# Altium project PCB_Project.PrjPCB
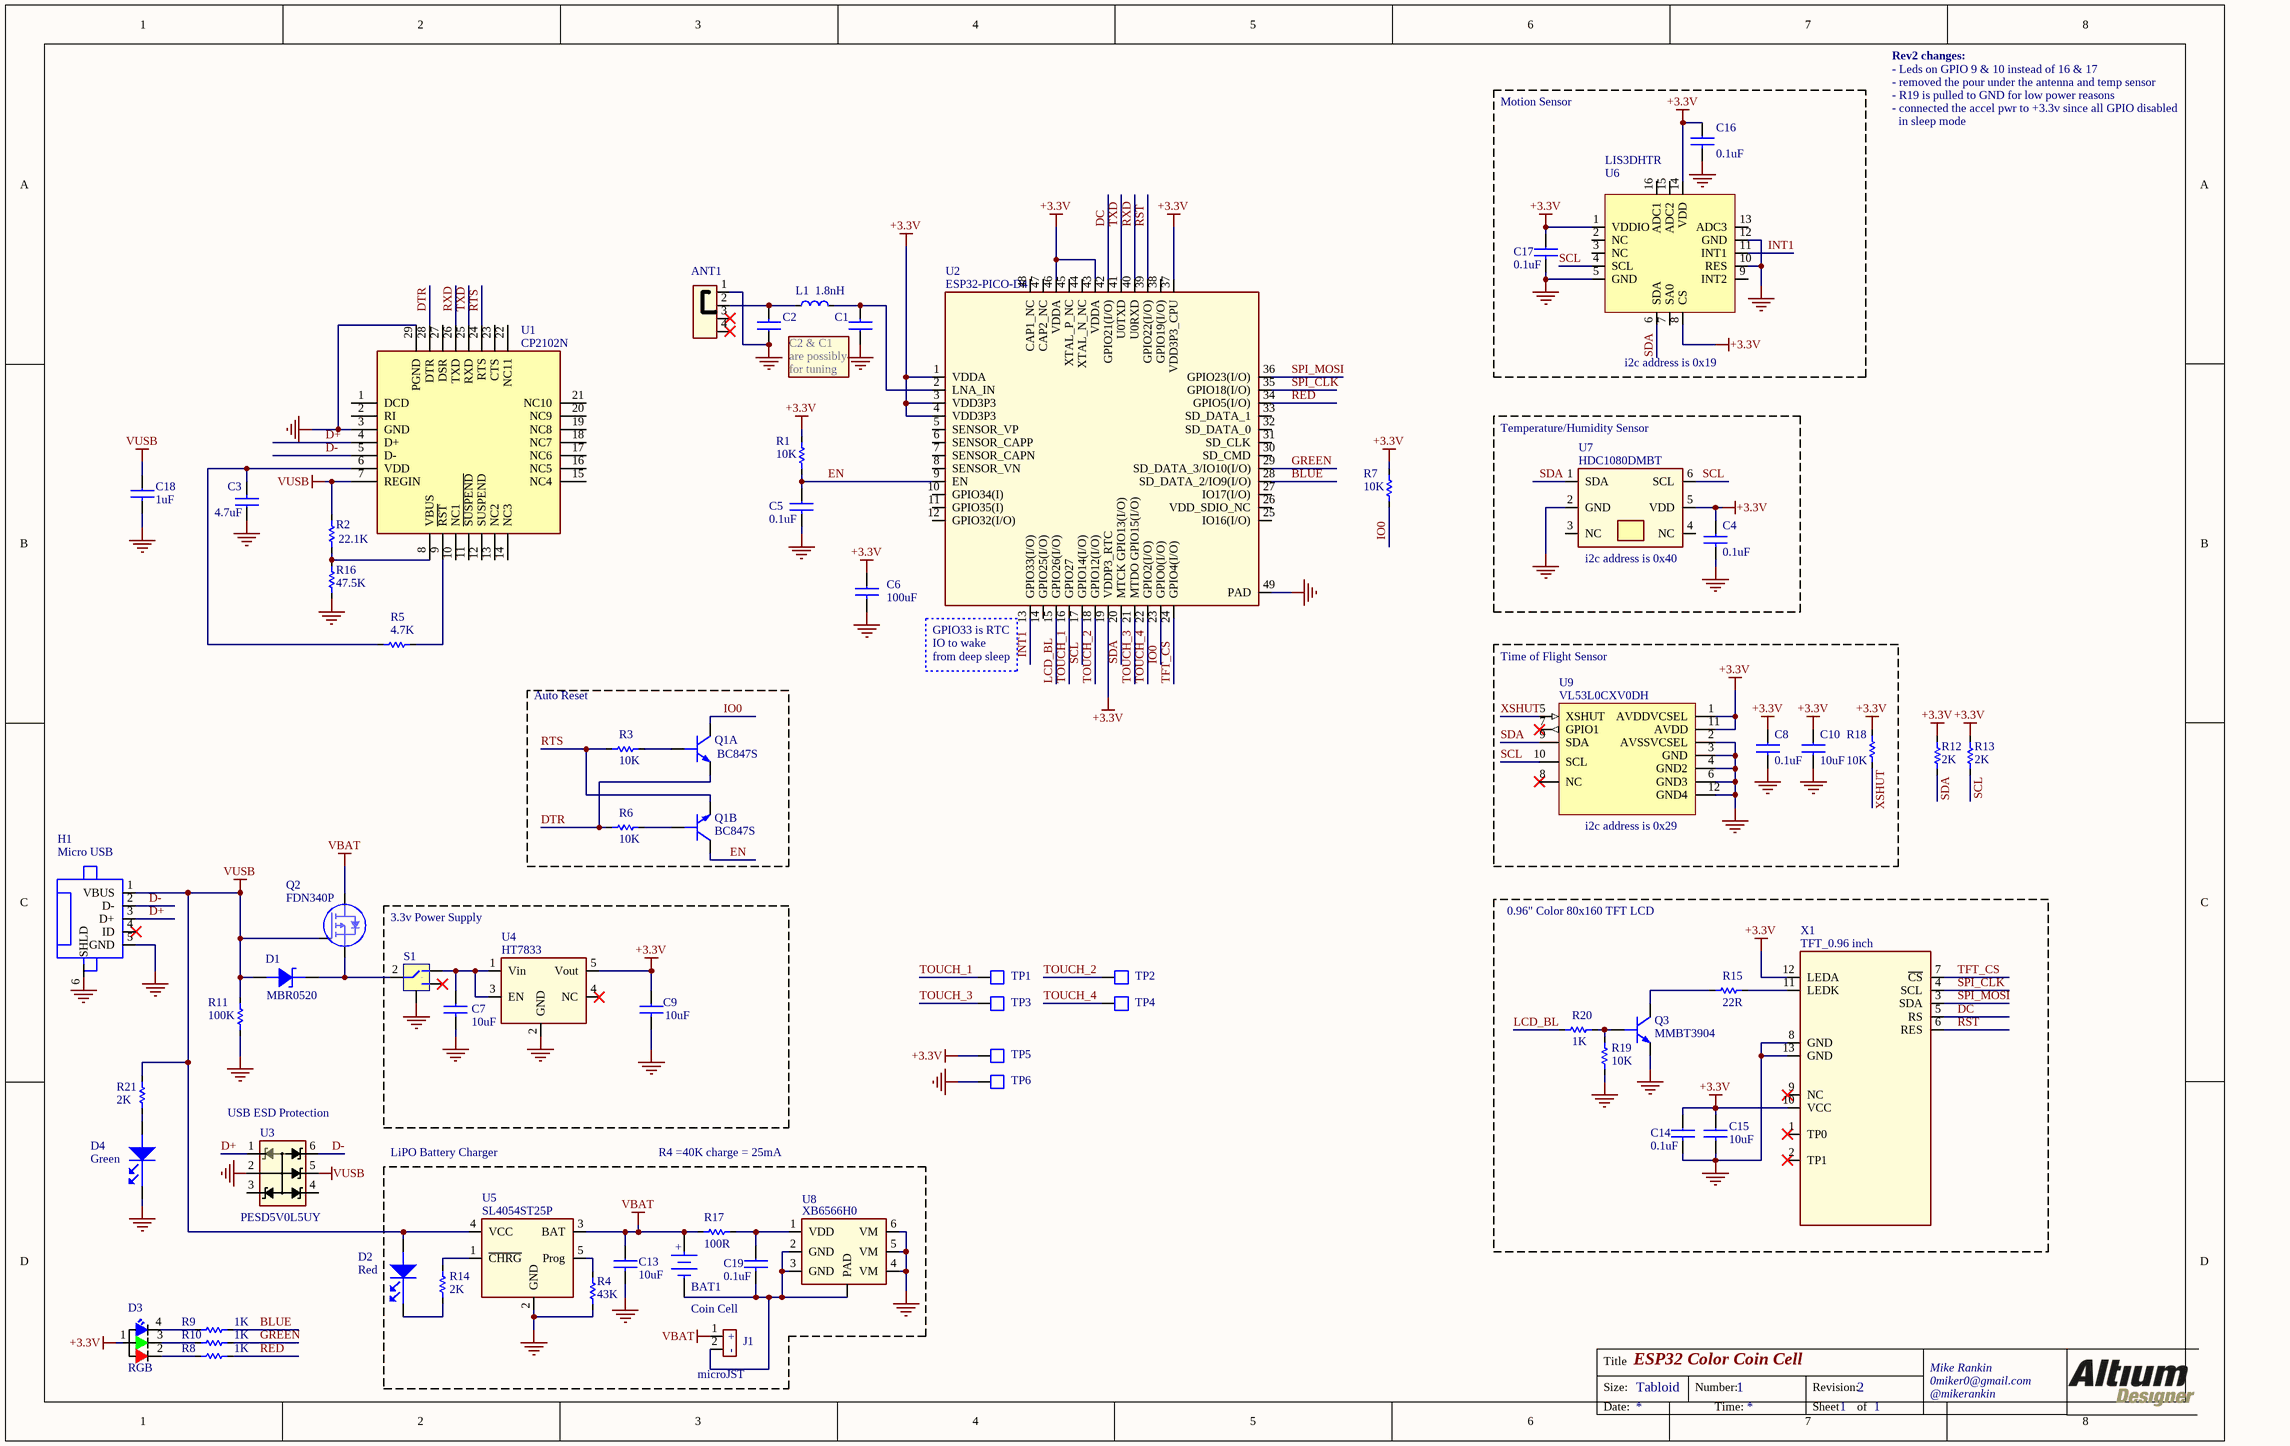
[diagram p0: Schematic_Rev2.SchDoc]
1 sheet, 67 parts. Net scope: global (net labels, ports and power ports of the same name join across sheets).
Board file: PCB_Rev2.PcbDoc

## Sheet Schematic_Rev2.SchDoc: ESP32 Color Coin Cell
size Tabloid; DrawnBy: x; Engineer: x; Address1: Mike Rankin; Address2: 0miker0@gmail.com; Address3: @mikerankin; DocumentNumber: 1; Revision: 2; SheetNumber: 1; SheetTotal: 1

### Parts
ANT1  RF ANT 2.4GHZ STAMPED MET SLD  [PRO-OB-440]  (value not drawn)
BAT1  BATTERY-HOLDER (2450)  [BU2450SM-JJ-GTR]  (value not drawn)
C1  (no value)  [CAPC1005X56N]  (no BOM)
C2  (no value)  [CAPC1005X56N]  (no BOM)
C3  4.7uF  [CAPC1005X56N]
C4  0.1uF  [CAPC1005X56N]
C5  0.1uF  [CAPC1005X56N]
C6  100uF  [CAPC3216X160L]
C7  10uF  [CAPC2012X140N]
C8  0.1uF  [CAPC1005X56N]
C9  10uF  [CAPC2012X140N]
C10  10uF  [CAPC2012X140N]
C13  10uF  [CAPC2012X140N]
C14  0.1uF  [CAPC1005X56N]
C15  10uF  [CAPC2012X140N]
C16  0.1uF  [RESC1005X40L]
C17  0.1uF  [CAPC1005X56N]
C18  1uF  [CAPC1005X56N]
C19  0.1uF  [CAPC1005X56N]
D1  MBR0520  [SOD123]
D2  value Red  [LED1608X55N-RED]  (hidden comment: LED_0603)
D3  RGB  [FC-B1010RGBT-HG]
D4  value Green  [LED1608X55N-GREEN]  (hidden comment: LED_0603)
H1  Micro USB  [1981584-1]
J1  CON2  [JST_Micro_2PIN]  (value not drawn)  (no BOM)
L1  value 1.8nH  [RESC1005X40L]  (hidden comment: Inductor)
Q1  BC847S  [SOT65P210X110-6N]  (parts A,B of 2)
Q2  FDN340P  [SOT95P240X110-3N]
Q3  MMBT3904  [SOT95P240X110-3N]
R1  10K  [RESC1005X40L]
R2  22.1K  [RESC1005X40L]
R3  10K  [RESC1005X40L]
R4  43K  [RESC1005X40L]
R5  4.7K  [RESC1005X40L]
R6  10K  [RESC1005X40L]
R7  10K  [RESC1005X40L]
R8  1K  [RESC1005X40L]
R9  1K  [RESC1005X40L]
R10  1K  [RESC1005X40L]
R11  100K  [RESC1005X40L]
R12  2K  [RESC1005X40L]
R13  2K  [RESC1005X40L]
R14  2K  [RESC1005X40L]
R15  22R  [RESC1005X40L]
R16  47.5K  [RESC1005X40L]
R17  100R  [RESC1005X40L]
R18  10K  [RESC1005X40L]
R19  10K  [RESC1005X40L]
R20  1K  [RESC1005X40L]
R21  2K  [RESC1005X40L]
S1  SWITCH SLIDE  [K3-1296S-E1]  (value not drawn)
TP1  Test Point, 1mm Top Layer  [TP100TL]  (value not drawn)  (no BOM)
TP2  Test Point, 1mm Top Layer  [TP100TL]  (value not drawn)  (no BOM)
TP3  Test Point, 1mm Top Layer  [TP100TL]  (value not drawn)  (no BOM)
TP4  Test Point, 1mm Top Layer  [TP100TL]  (value not drawn)  (no BOM)
TP5  Test Point, 1mm Top Layer  [TP100TL]  (value not drawn)  (no BOM)
TP6  Test Point, 1mm Top Layer  [TP100TL]  (value not drawn)  (no BOM)
U1  CP2102N  [28-QFN]
U2  ESP32-PICO-D4  [QFN48]
U3  PESD5V0L5UY  [SOT65P210X110-6N]
U4  HT7833  [SOT95P280X144-5N]
U5  SL4054ST25P  [SOT95P280X144-5N]
U6  LIS3DHTR  [QFN3X3_16_1.2]
U7  HDC1080DMBT  [HDC1080]
U8  XB6566H0  [DFN-6 2x2mm]
U9  VL53L0CXV0DH  [VL53L0CXV0DH]
X1  TFT_0.96 inch  [TFT_GLASS 0.96 INCH]

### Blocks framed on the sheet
Auto Reset: Q1 R3 R6
3.3v Power Supply: C7 C9 S1 U4
0.96" Color 80x160 TFT LCD: C14 C15 Q3 R15 R19 R20 X1

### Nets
+3.3V: C4.1 C6.1 C8.1 C9.1 C10.1 C14.1 C15.1 C16.1 C17.1 D3.1 R1.1 R7.1 R12.2 R13.2 R18.1 TP5.1 U2.1(VDDA) U2.3(VDD3P3) U2.4(VDD3P3) U2.19(VDDP3_RTC) U2.37(VDD3P3_CPU) U2.43(VDDA) U2.46(VDDA) U4.5(Vout) U6.1(VDDIO) U6.8(CS) U6.14(VDD) U7.5(VDD) U9.1(AVDDVCSEL) U9.11(AVDD) X1.10(VCC) X1.12(LEDA)
GND: ANT1.1 C1.1 C2.1 C3.1 C4.2 C5.2 C6.2 C7.2 C8.2 C9.2 C10.2 C13.2 C14.2 C15.2 C16.2 C17.2 C18.2 D4.1(CATHODE) H1.5(GND) H1.6(SHLD) Q3.2(E) R4.2 R11.2 R16.1 R19.2 S1.4 TP6.1 U1.3(GND) U1.29(PGND) U2.49(PAD) U3.2 U4.2(GND) U5.2(GND) U6.5(GND) U6.10(RES) U6.12(GND) U7.2(GND) U8.4(VM) U8.5(VM) U8.6(VM) U9.2(AVSSVCSEL) U9.3(GND) U9.4(GND2) U9.6(GND3) U9.12(GND4) X1.8(GND) X1.13(GND)
VBAT: BAT1.1(+) C13.1 J1.1 Q2.3(D) R17.1 U5.3(BAT)
VUSB: C18.1 D1.2(Annode) D2.2(ANODE) H1.1(VBUS) Q2.1(G) R2.2 R11.1 R21.2 U1.7(REGIN) U3.5 U5.4(VCC)
BLUE: R9.2 U2.28(SD_DATA_2/IO9(I/O))
D+: H1.3(D+) U1.4(D+) U3.1
D-: H1.2(D-) U1.5(D-) U3.6
DC: U2.42(GPIO21(I/O)) X1.5(RS)
DTR: Q1.1(E1) R6.2 U1.28(DTR)
EN: C5.1 Q1.3(C2) R1.2 U2.9(EN)
GREEN: R10.2 U2.29(SD_DATA_3/IO10(I/O))
INT1: U2.13(GPIO33(I/O)) U6.11(INT1)
IO0: Q1.6(C1) R7.2 U2.23(GPIO0(I/O))
LCD_BL: R20.1 U2.15(GPIO26(I/O))
RED: R8.2 U2.34(GPIO5(I/O))
RST: U2.39(GPIO22(I/O)) X1.6(RES)
RTS: Q1.4(E2) R3.2 U1.24(RTS)
RXD: U1.26(TXD) U2.40(U0RXD)
SCL: R13.1 U2.17(GPIO14(I/O)) U6.4(SCL) U7.6(SCL) U9.10(SCL)
SDA: R12.1 U2.20(MTCK_GPIO13(I/O)) U6.6(SDA) U7.1(SDA) U9.9(SDA)
SPI_CLK: U2.35(GPIO18(I/O)) X1.4(SCL)
SPI_MOSI: U2.36(GPIO23(I/O)) X1.3(SDA)
TFT_CS: U2.24(GPIO4(I/O)) X1.7(~{CS})
TOUCH_1: TP1.1 U2.16(GPIO27)
TOUCH_2: TP2.1 U2.18(GPIO12(I/O))
TOUCH_3: TP3.1 U2.21(MTDO_GPIO15(I/O))
TOUCH_4: TP4.1 U2.22(GPIO2(I/O))
TXD: U1.25(RXD) U2.41(U0TXD)
XSHUT: R18.2 U9.5(XSHUT)
NetANT1_2: ANT1.2 C2.2 L1.1
NetBAT1_2: BAT1.2(-) C19.2 J1.2 U8.2(GND) U8.3(GND) U8.7(PAD)
NetC1_2: C1.2 L1.2 U2.2(LNA_IN)
NetC3_2: C3.2 R5.1 U1.6(VDD)
NetC7_1: C7.1 S1.1 U4.1(Vin) U4.3(EN)
NetC19_1: C19.1 R17.2 U8.1(VDD)
NetD1_1: D1.1(Cathode) Q2.2(S) S1.2
NetD2_1: D2.1(CATHODE) R14.1
NetD3_2: D3.2 R8.1
NetD3_3: D3.3 R10.1
NetD3_4: D3.4 R9.1
NetD4_2: D4.2(ANODE) R21.1
NetQ1_2: Q1.2(B1) R3.1
NetQ1_5: Q1.5(B2) R6.1
NetQ3_1: Q3.1(B) R19.1 R20.2
NetQ3_3: Q3.3(C) R15.2
NetR2_1: R2.1 R16.2 U1.8(VBUS)
NetR4_1: R4.1 U5.5(Prog)
NetR5_2: R5.2 U1.9(~{RST})
NetR14_2: R14.2 U5.1(~{CHRG})
NetR15_1: R15.1 X1.11(LEDK)

Not connected (* = marked no-connect by the designer): ANT1 3* 4*; H1 4(ID)*; S1 3*; U1 1(DCD) 2(RI) 10(NC1) 11(~{SUSPEND}) 12(SUSPEND) 13(NC2) 14(NC3) 15(NC4) 16(NC5) 17(NC6) 18(NC7) 19(NC8) 20(NC9) 21(NC10) 22(NC11) 23(CTS) 27(DSR); U2 5(SENSOR_VP) 6(SENSOR_CAPP) 7(SENSOR_CAPN) 8(SENSOR_VN) 10(GPIO34(I)) 11(GPIO35(I)) 12(GPIO32(I/O)) 14(GPIO25(I/O)) 25(IO16(I/O)) 26(VDD_SDIO_NC) 27(IO17(I/O)) 30(SD_CMD) 31(SD_CLK) 32(SD_DATA_0) 33(SD_DATA_1) 38(GPIO19(I/O)) 44(XTAL_N_NC) 45(XTAL_P_NC) 47(CAP2_NC) 48(CAP1_NC); U3 3 4; U4 4(NC)*; U6 2(NC) 3(NC) 7(SA0) 9(INT2) 13(ADC3) 15(ADC2) 16(ADC1); U7 3(NC) 4(NC); U9 7(GPIO1)* 8(NC)*; X1 1(TP0)* 2(TP1)* 9(NC)*

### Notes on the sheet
- Rev2 changes:
- - Leds on GPIO 9 & 10 instead of 16 & 17
- - removed the pour under the antenna and temp sensor
- Motion Sensor
- - R19 is pulled to GND for low power reasons
- - connected the accel pwr to +3.3v since all GPIO disabled
- in sleep mode
- C2 & C1
- are possibly
- for tuning
- (near U6) i2c address is 0x19
- (near U7) Temperature/Humidity Sensor
- i2c address is 0x40
- (near U2) GPIO33 is RTC
- (near U2) IO to wake
- (near U2) from deep sleep
- Time of Flight Sensor
- (near U9) i2c address is 0x29
- (near U3) USB ESD Protection
- LiPO Battery Charger
- R4 =40K charge = 25mA
- Coin Cell
- (near J1) microJST
- Labels drawn without touching a wire or pin: ~{}

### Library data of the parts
ANT1 = PRO-OB-440: Manufacturer: Proant AB; Vendor: Digi-Key
BAT1 = BU2450SM-JJ-GTR: HOLDER,BATT,COIN,24.5MM,SMT; Manufacturer: MPD; Value: Coin Cell Holder; Vendor: LCSC
C1 C2 = CAP_0402: DNP
C3 = CAP_0603: CAP CER 4.7uF 16V 0402; Vendor: LCSC
C4 C5 C8 C17 C19 = CAP_0402: CAP CER 0.1uF 0402; PartNumber: TCC0402X5R104M160AT; Manufacturer: CCTC; Vendor: LCSC
C6 = CAP_1206: CAP CER 100uF 6.3V 1206; PartNumber: JMK316BJ107ML-T; Manufacturer: Taiyo Yuden; Vendor: LCSC
C7 C9 C10 = CAP_0805: CAP 10uF 0805; Manufacturer: Murata; PartNumber: GRM21BB31C106KE15L; Vendor: LCSC
C13 = CAP_0805: CAP CER 10uF 16V 0805; PartNumber: CL21A106KOQNNNG; Manufacturer: Samsung; Vendor: LCSC
C14 C16 = CAP_0402: CAP CER 0.1uF 0402; Vendor: LCSC
C15 = CAP_0805: CAP 10uF 0805; Vendor: LCSC
C18 = CAP_0603: CAP CER 1uF 16V 0402; Vendor: LCSC
D1 = MBR0520-TP: DIODE SCHOTTKY 20V 500MA SOD123; Manufacturer: CJ; Vendor: LCSC
D2 = LED_0603: LED RED CLEAR 0603 SMD; Manufacturer: FNO; PartNumber: FC-DA1608HRK-620D; Vendor: LCSC
D3 = FC-B1010RGBT-HG: LED,RGB LED,SMD,RoHS; Manufacturer: Foshan; Vendor: LCSC; Value: RGB Led
D4 = LED_0603: LED XXXX CLEAR 0603 SMD; Manufacturer: Lite-On; Vendor: Digi-Key
H1 = 1981584-1: CONN RCPT MICRO USB TYPE AB; Manufacturer: REG CON; PartNumber: C21377; Vendor: LCSC
J1 = JST_Micro_CONN_2PIN: JST MIcro CONN 2POS
L1 = Inductor: Inductor 1.8nH 0402; PartNumber: BKW0603UC1N8KGT; Manufacturer: GFBE; Vendor: LCSC
Q1 = BC847S: TRANS 2NPN 44V 0.1A SC-70-6; Manufacturer: Changjiang; Vendor: LCSC
Q2 = FDN340P: MOSFET P-CH 20V 2A SOT-23; Manufacturer: On Semi; Vendor: LCSC; Value: Mosfet P-H
Q3 = MMBT3904-TP: TRANSISTOR NPN GP 40V SOT23; Manufacturer: Micro Commercial
R1 R3 R6 R7 R18 R19 = RES_0402: RES SMD 10K OHM 0402; PartNumber: RC-02W1002FT; Manufacturer: Guangdong; Vendor: LCSC
R2 = RES_0603: RES SMD 22.1K OHM 0402; Manufacturer: Yageo; PartNumber: RC0402FR-0722K1L; Vendor: LCSC
R4 = RES_0603: RES SMD 43K OHM 0402; Manufacturer: Uniroyal; PartNumber: 0402WGF4302TCE; Vendor: LCSC
R5 = RES_0603: RES SMD 4.7K OHM 0402; Manufacturer: Yageo; PartNumber: RC0402FR-074K7L; Vendor: LCSC
R8-R10 R20 = RES_0402: RES SMD 1K OHM 0402; PartNumber: RC0402FR-071KL; Manufacturer: Yageo; Vendor: LCSC
R11 = RES_0603: RES SMD 100K OHM 0402; Manufacturer: Uniroyal Elec; PartNumber: 0402WGF1003TCE; Vendor: LCSC
R12 R13 = RES_0402: RES 2K 0402; Vendor: LCSC
R14 R21 = RES_0603: RES SMD 2K OHM 1% 1/10W 0402; Manufacturer: LIZ Elec; PartNumber: CR0402FF2001G; Vendor: LCSC
R15 = RES_0402: RES 22R 0402; Vendor: LCSC
R16 = RES_0603: RES SMD 47.5K OHM 0402; Manufacturer: Yageo; PartNumber: RC0402FR-0747K5L; Vendor: LCSC
R17 = RES_0603: RES SMD 100R OHM 1% 1/10W 0402; Manufacturer: Yageo; PartNumber: RC0402FR-07100RL; Vendor: LCSC
S1 = K3-1296S-E1: SWITCH SLIDE SMD; Manufacturer: Korean Hroparts Elec; Vendor: LCSC
U1 = CP2102N: IC BRIDGE USB TO UART 28QFN; Manufacturer: Silicon Labs; PartNumber: CP2102N-A01-GQFN28; Vendor: LCSC
U2 = ESP32-PICO-D4: RF Transceiver ICs QFN-48_7x7x05P RoHS; Manufacturer: Espressif; Vendor: LCSC
U3 = PESD5V0L5UY: TVS SOT-363 RoHS; Manufacturer: Yenji; Vendor: LCSC; Value: ESD
U4 = HT7833: IC LDO 3.3V 0.5A SOT23-5; Manufacturer: Holtek; Vendor: LCSC
U5 = SL4054ST25P: Charger IC Lithium-Ion/Polymer SOT23-5; Manufacturer: Techfuse; Vendor: LCSC
U6 = E-05-177: IC ACCEL 2-16G I2C/SPI 16LGA; Manufacturer: STMicro; Vendor: LCSC
U7 = HDC1080DMBT: Humidity/Temperature Sensor; Manufacturer: Texas Instruments; Vendor: LCSC
U8 = XB6566H0: IC Battery Protection; Manufacturer: XySemi; Vendor: LCSC
U9 = VL53L0CXV0DH: IC,LASER SENSOR,12pin; Manufacturer: ST MICRO; Part Number: VL53L0CXV0DH/1
X1 = TFT_GLASS 0.96 INCH COLOR: 0.96 INCH TFT GLASS COLOR; PartNumber: ER-TFT0.96-1; Manufacturer: BuyDisplay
